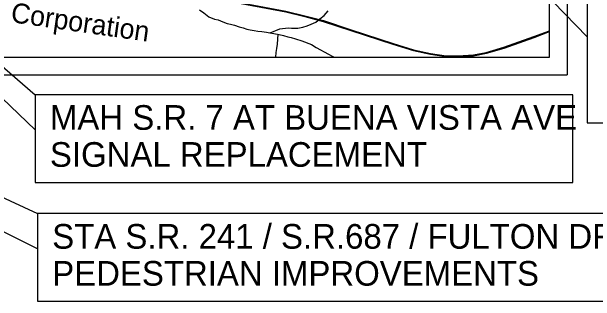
# Model space of a CAD drawing. Extents: x 25.6 to 80.6, y 0.2 to 24.5.
# Drawn here: x 44.756 to 48.073, y 12.944 to 14.588 of the extents above; entities that cross this region are included whole.
import ezdxf

# ---------------------------------------------------------------- set-up
doc = ezdxf.new("R2010")
doc.units = 0
for name, color, linetype in [('GM_X_Minor_Lake', 7, 'Continuous'), ('GM_X_Minor_River', 7, 'Continuous'), ('GM_X_Rail_Line', 7, 'Continuous'), ('GM_X_Rail_Line_Text', 7, 'Continuous'), ('SH_Data', 7, 'Continuous'), ('SH_Text', 7, 'Continuous')]:
    doc.layers.add(name, color=color, linetype=linetype)

msp = doc.modelspace()

# ---------------------------------------------------------------- linework, layer by layer
at = {"layer": 'GM_X_Minor_Lake'}
msp.add_lwpolyline([(46.2243, 14.4683), (46.2804, 14.4904), (46.3266, 14.4956), (46.3471, 14.4952), (46.3828, 14.4949), (46.4116, 14.5006), (46.4357, 14.507), (46.4584, 14.518), (46.4848, 14.529), (46.508, 14.5468), (46.5313, 14.5669), (46.5552, 14.5923)], dxfattribs=at)
at = {"layer": 'GM_X_Minor_River'}
for points in [[(45.823, 14.5995), (45.8483, 14.5809), (45.8759, 14.5584), (45.9079, 14.5452), (45.9292, 14.541), (45.9559, 14.5307), (45.9811, 14.5219), (46.0001, 14.5176), (46.0222, 14.5111), (46.0489, 14.5024), (46.071, 14.4958), (46.0915, 14.4893), (46.1113, 14.485), (46.1341, 14.4808), (46.1547, 14.478), (46.1775, 14.4753), (46.2033, 14.4711), (46.2238, 14.4684), (46.2459, 14.4641), (46.2756, 14.4592), (46.2999, 14.4535), (46.3258, 14.4462), (46.3448, 14.4412), (46.3692, 14.4332), (46.4058, 14.423), (46.4592, 14.401), (46.486, 14.3847), (46.5104, 14.3706), (46.5311, 14.3595), (46.5563, 14.3477), (46.5777, 14.3358), (46.5891, 14.3303)], [(46.269, 14.4603), (46.2642, 14.4028), (46.2615, 14.38), (46.2572, 14.3564), (46.2563, 14.3303)]]:
    msp.add_lwpolyline(points, dxfattribs=at)
at = {"layer": 'GM_X_Rail_Line'}
for points in [[(44.4128, 14.8771), (44.4231, 14.8756), (44.5249, 14.8648), (44.6048, 14.8557), (44.6465, 14.8507), (44.805, 14.8274), (45.0669, 14.7959), (45.2891, 14.7633), (46.0102, 14.6483), (46.3148, 14.5918), (46.4227, 14.5651), (46.528, 14.5372), (46.6857, 14.4857), (46.9234, 14.4078), (47.0403, 14.372), (47.1373, 14.3511), (47.2255, 14.3378), (47.2936, 14.3374), (47.3809, 14.3425), (47.4529, 14.3573), (47.553, 14.386), (47.7232, 14.4468), (47.8128, 14.4801)], [(44.4128, 14.8724), (44.4226, 14.871), (44.5243, 14.8601), (44.6043, 14.851), (44.6459, 14.846), (44.8044, 14.8227), (45.0663, 14.7912), (45.2884, 14.7586), (46.0094, 14.6437), (46.3138, 14.5872), (46.4216, 14.5606), (46.5266, 14.5327), (46.6843, 14.4812), (46.9219, 14.4033), (47.0391, 14.3674), (47.1365, 14.3464), (47.2252, 14.3331), (47.2937, 14.3327), (47.3816, 14.3378), (47.454, 14.3527), (47.5545, 14.3816), (47.7248, 14.4424), (47.8128, 14.4751)]]:
    msp.add_lwpolyline(points, dxfattribs=at)
at = {"layer": 'SH_Data'}
for p in [(47.9128, 17.8303), (37.5128, 14.2303)]:
    msp.add_line(p, (47.9128, 14.2303), dxfattribs=at)
at = {"layer": 'SH_Text'}
for points in [[(44.4128, 14.3303), (47.8128, 14.3303), (47.8128, 17.7303), (44.4128, 17.7303)], [(44.9027, 13.4418), (44.9027, 13.2418), (39.3128, 16.0303)], [(48.0273, 14.646), (48.0273, 14.446), (46.473, 16.0447)], [(44.8898, 14.1167), (44.8898, 13.9167), (42.7135, 16.0036)], [(50.7329, 14.646), (48.0273, 14.646), (48.0273, 13.9578), (50.7329, 13.9578)], [(47.9449, 14.1167), (44.8898, 14.1167), (44.8898, 13.6188), (47.9449, 13.6188)], [(48.1867, 13.4418), (44.9027, 13.4418), (44.9027, 12.9439), (48.1867, 12.9439)]]:
    msp.add_lwpolyline(points, close=True, dxfattribs=at)

# ---------------------------------------------------------------- texts
at = {"layer": 'GM_X_Rail_Line_Text'}
msp.add_text('Corporation', height=0.113258, rotation=351.8832, dxfattribs=at).set_placement((44.7466, 14.5293))
at = {"layer": 'SH_Text'}
for s, p in [('MAH S.R. 7 AT BUENA VISTA AVE', (44.9732, 13.9175)), ('SIGNAL REPLACEMENT', (44.9732, 13.7075)), ('STA S.R. 241 / S.R.687 / FULTON DR', (44.9861, 13.2426)), ('PEDESTRIAN IMPROVEMENTS', (44.9861, 13.0326))]:
    msp.add_text(s, height=0.14, dxfattribs=at).set_placement(p)

doc.saveas('drawing.dxf')
